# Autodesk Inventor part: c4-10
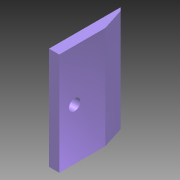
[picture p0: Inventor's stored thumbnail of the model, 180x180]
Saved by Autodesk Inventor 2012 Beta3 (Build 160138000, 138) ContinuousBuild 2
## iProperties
Created: 2010-11
Part Number: c4-10
Material: Default
Document SubType Name: Modeling
Designer: Beta-8540w
Density: 1 g/cm^3
Author: Beta-8540w
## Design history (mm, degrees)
sketch "Sketch1"
  geometry: L1 (0, 0)-(10, 0); L2 (10, 0)-(10, 70); L3 (10, 70)-(0, 70); L4 (0, 70)-(0, 0); L5 (3, 67)-(10, 45); L6 (0, 70)-(3, 67); 1 further point
  constraints: 12 end point, 2 parallel, 2 point on line, 1 horizontal, 1 perpendicular
  dimensions: "d0" = 10 distance of L3.end L2.end; "d1" = 70 distance of L2.end L1.end; "d3" = 25 vertical distance of point (2.045, 70) L5.end; "d6" = 45 deg angle of L4 L6; "d7" = 3 distance from line of L4 L5.start
extrude "Extrusion1" new body sketch "Sketch1" stored distance "d4" = 100; taper "d5" = 0 deg
hole "Hole1" diameter "d10" = 11; stored, may be unused: countersink angle "d14" = 90 deg, drill point angle "d16" = 118 deg; dims "d8" = 50, "d9" = 15, "d11" = 6, "d12" = 4, "d13" = 2, "d15" = 8
body "Solid1"
